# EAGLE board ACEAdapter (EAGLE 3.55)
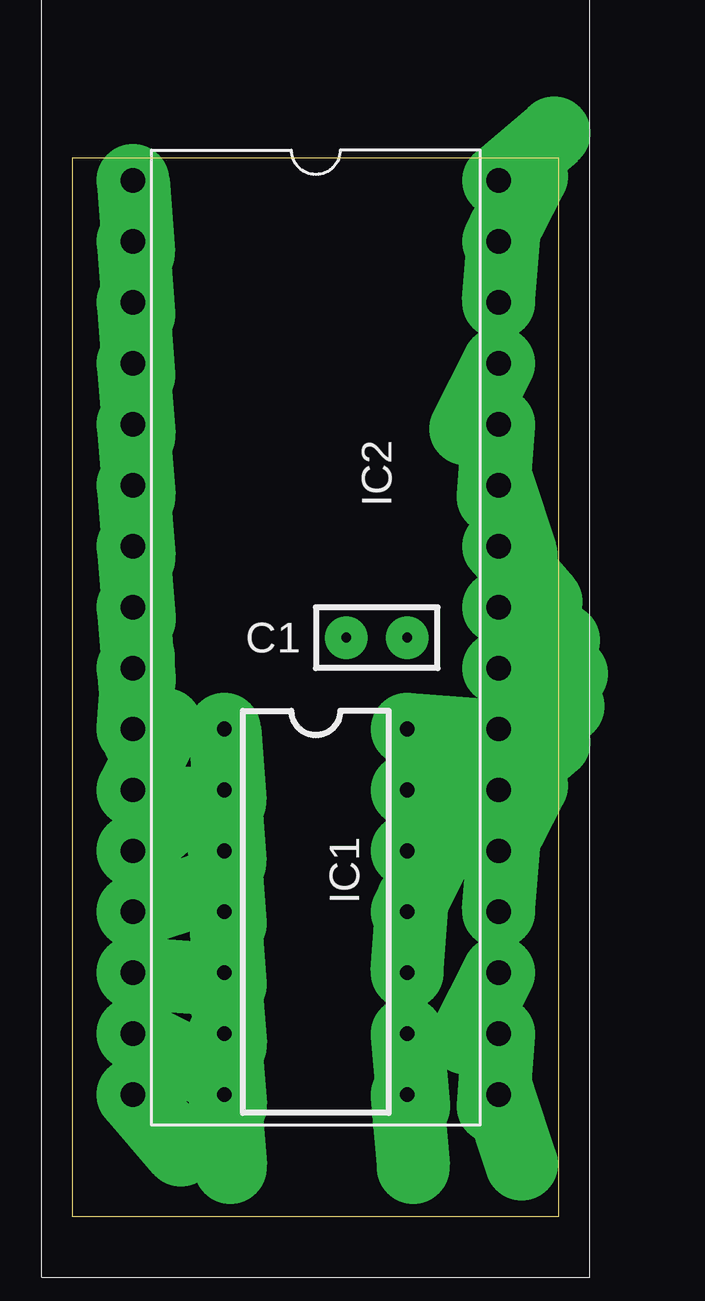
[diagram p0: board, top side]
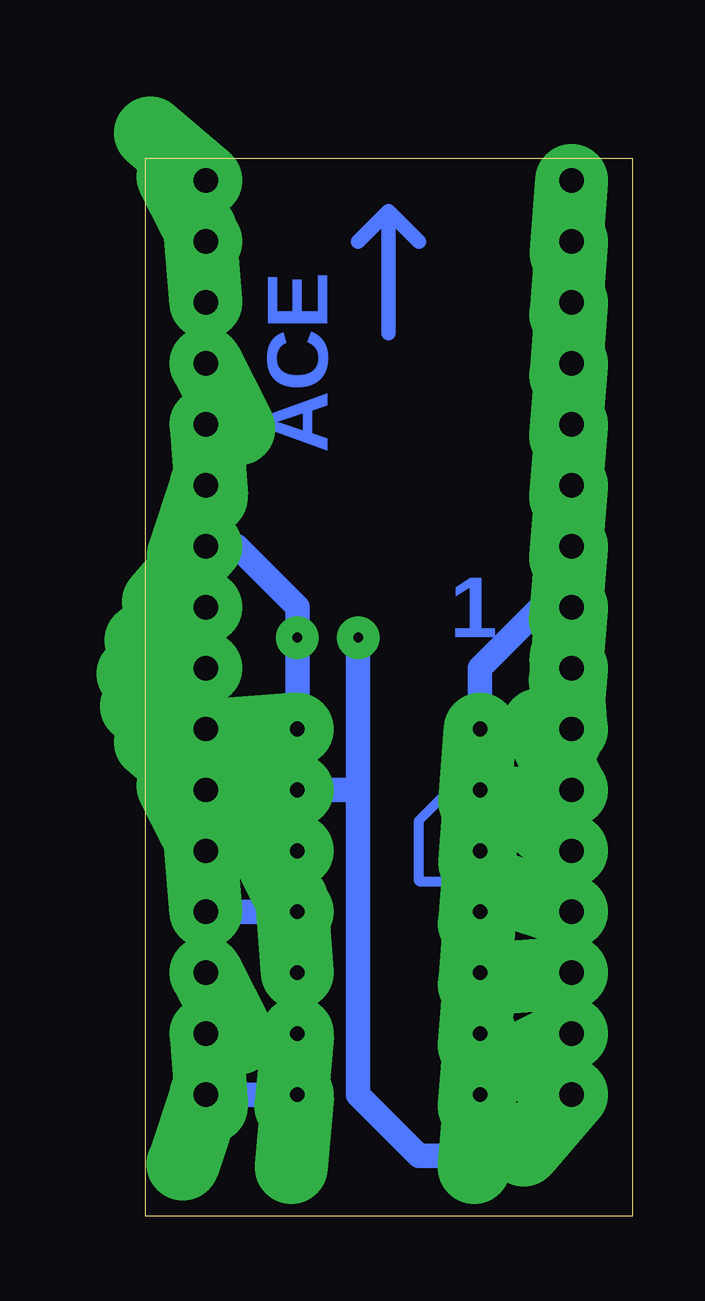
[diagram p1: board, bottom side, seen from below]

Size 20.3 x 44.12 mm. Coordinates in mm from the lower left corner, seen from the top.
Outline: 0,0 20.3,0 20.3,44.12 0,44.12 0,0
Copper layers used: Bottom

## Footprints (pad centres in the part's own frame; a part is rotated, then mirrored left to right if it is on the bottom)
RM2,5 = drill 0.406 pad 1.778 round:  0,0;  2.54,0
L-14B = drill 0.61 pad 3.048 offset:  0,0;  2.54,0;  5.08,0;  7.62,0;  10.16,0;  12.7,0;  15.24,0;  15.24,7.62;  12.7,7.62;  10.16,7.62;  7.62,7.62;  5.08,7.62;  2.54,7.62;  0,7.62
XTO_32 = drill 1.016 pad 3.048 offset:  0,0;  2.54,0;  15.24,0;  17.78,0;  5.08,0;  7.62,0;  12.7,0;  10.16,0;  20.32,0;  22.86,0;  25.4,0;  27.94,0;  30.48,0;  33.02,0;  35.56,0;  38.1,0;  38.1,15.24;  35.56,15.24;  33.02,15.24;  30.48,15.24;  27.94,15.24;  25.4,15.24;  22.86,15.24;  20.32,15.24;  17.78,15.24;  15.24,15.24;  12.7,15.24;  10.16,15.24;  7.62,15.24;  5.08,15.24;  2.54,15.24;  0,15.24

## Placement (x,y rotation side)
C1  100n  [RM2,5]  13.97,24.13 180 top
IC1  ACESockel  [L-14B]  6.35,20.32 270 top
IC2  TEXTOEP_32  [XTO_32]  2.54,43.18 270 top

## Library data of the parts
C1 IC1 = holg_plt
IC2 = galeprom

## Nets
CLK8: IC1. IC2.
CLK14: IC1. IC2.
GND: C1. IC1. IC2.
LOAD: IC1. IC2.
SI: IC1. IC2.
SO_8: IC1. IC2.
VCC: C1. IC1. IC2.

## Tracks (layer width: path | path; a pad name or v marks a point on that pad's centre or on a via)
CLK8
  Bottom 1.016: 17.78,12.7 13.97,12.7
CLK14
  Bottom 1.016: 17.78,5.08 13.97,5.08
GND
  Bottom 1.016: 2.54,5.08 5.08,2.54 8.89,2.54 11.43,5.08 11.43,17.78 | 11.43,17.78 13.97,17.78 | 11.43,17.78 C1.
LOAD
  Bottom 1.016: 6.35,20.32 6.35,22.86 3.81,25.4 2.54,25.4
N$2
  Bottom 0.61: 10.16,36.83 10.16,41.91 | 8.89,40.64 10.16,41.91 | 10.16,41.91 11.43,40.64
SI
  Bottom 0.406: 2.54,12.7 3.81,13.97 8.89,13.97 8.89,16.51 7.62,17.78 6.35,17.78
SO_8
  Bottom 1.016: 17.78,15.24 13.97,15.24
VCC
  Bottom 1.016: IC1. 13.97,24.13 13.97,25.4 16.51,27.94 17.78,27.94

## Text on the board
Bottom: ACE | 1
